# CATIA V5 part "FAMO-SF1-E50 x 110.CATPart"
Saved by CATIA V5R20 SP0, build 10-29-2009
Part number: FAMO-SF1-E50 x 110
Definition: NONE
Nomenclature: FAMO-SF1-E50 x 110
Source: Unknown
Description: FAMO-SF1-E50 x 110
Bounding box of the stored display mesh (mm): x -75 to 35, y -39.5 to 39.5, z -39.5 to 39.5
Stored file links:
  C:\Users\Utente\Desktop\IO LAVORO\3D X SITO CF\X SITO\FAMO\FAMO-SF1-E50 x 110.CATPart

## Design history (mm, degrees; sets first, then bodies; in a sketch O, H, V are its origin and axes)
Body1 "FAMO-SF1-E50 x 110" (main body)
  Solid1: solid without history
